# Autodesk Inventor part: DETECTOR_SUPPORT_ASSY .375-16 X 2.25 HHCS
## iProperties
Shininess: 64.0
Length Units: 11272
Angle Units: 11279
Time Units: 11290
Mass Units: 11286
Length Display Precision: 3
Angle Display Precision: 2
Compacted: True
Part Number: DETECTOR_SUPPORT_ASSY .375-16 X 2.25 HHCS
Document SubType Name: Modeling
Created: 2004-08
Designer: John Blackburn
Material: STAINLESS_STEEL, AUSTENITIC
Manufacturer: Standard
Standards Organization: Custom
Density: 0.0
Volumn: 0.0
Area: 0.0
PropertySet Name: Model Information
Control State: 0
Master: False
Checked Out: False
Author: John Blackburn
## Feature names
1. Base1
